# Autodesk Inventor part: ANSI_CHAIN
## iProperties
Author: Ole Germer
Shininess: 64.0
Angle Display Precision: 2
Document Length Units: 11272
Document Angle Units: 11286
Document Time Units: 11279
Document Mass Units: 11290
Document Length Units Precision: 3
Document Angle Units Precision: 2
Compacted: True
PropertySet Name: _Private Model Information
Created: 2002-08
Part Number: ANSI_CHAIN
Material: ASTM A36 HRS
Document SubType Name: Modeling
Designer: Ole Germer
Control State: 0
Master: False
Checked Out: False
PropertySet Name: Design Tracking Control
Density: 0.0
Volumn: 0.0
Area: 0.0
PropertySet Name: Model Information
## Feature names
1. Extrusion1
2. Extrusion2
3. Extrusion3
4. Rectangular Pattern1
